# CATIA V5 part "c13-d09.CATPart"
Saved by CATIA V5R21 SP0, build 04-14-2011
Part number: Part1
Bounding box of the stored display mesh (mm): x -14.877 to 14.877, y 0 to 225, z -14.877 to 14.877
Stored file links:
  D:\CATIA V5R21 E-RESOURCES\CATIA-V5R21\catia-v5r21-Prts\c13_catia_v5r21_prt\c13_catia_v5r21_figr_13-36\c13-d09.CATPart
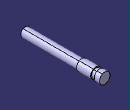
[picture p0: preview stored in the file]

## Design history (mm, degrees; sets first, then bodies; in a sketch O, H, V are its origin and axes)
Body1 (main body)
  Sketch1 on yz-plane, origin (0, 0, 0), H (0, 1, 0), V (0, 0, 1)
    axis line L1 (0, 0) -> (204.8018, 0)
    line L2 (0, 0) -> (0, 12.5)
    line L3 (160, 15) -> (200, 15)
    line L4 (200, 15) -> (200, 12.5)
    line L5 (200, 12.5) -> (210, 12.5)
    line L6 (210, 12.5) -> (210, 15)
    point P5 (210, 15)
    point P6 (210, 15)
    line L7 (210, 15) -> (225, 15)
    line L8 (225, 15) -> (225, 0)
    point P8 (225, 0)
    line L9 (225, 0) -> (0, 0)
    line L10 (160, 15) -> (160, 12.5)
    line L11 (160, 12.5) -> (0, 12.5)
    "Radius" L1 L7 = 15
    "Radius" L5 L1 = 12.5
    length L9 = 225
    length L5 = 10
    distance L4 L2 = 200
    "Radius" L11 L1 = 12.5
    length L11 = 160
    horizontal: L1 H, L3 H, L5 H, L7 H, L9 H, L11 H
    vertical: L2 V, L4 V, L6 V, L8 V, L10 V
    coincidence: P5 L3, P6 L3, P8 L1, P6 P5
  Shaft1: profile Sketch1, axis Sketch1.L1, angle 360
